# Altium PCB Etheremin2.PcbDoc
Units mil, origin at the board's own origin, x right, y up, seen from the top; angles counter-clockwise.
Board outline 6000 x 4000 mil, 2 copper layers (Top Layer, Bottom Layer); 40 components, 34 nets, 119 pads, 0 vias.
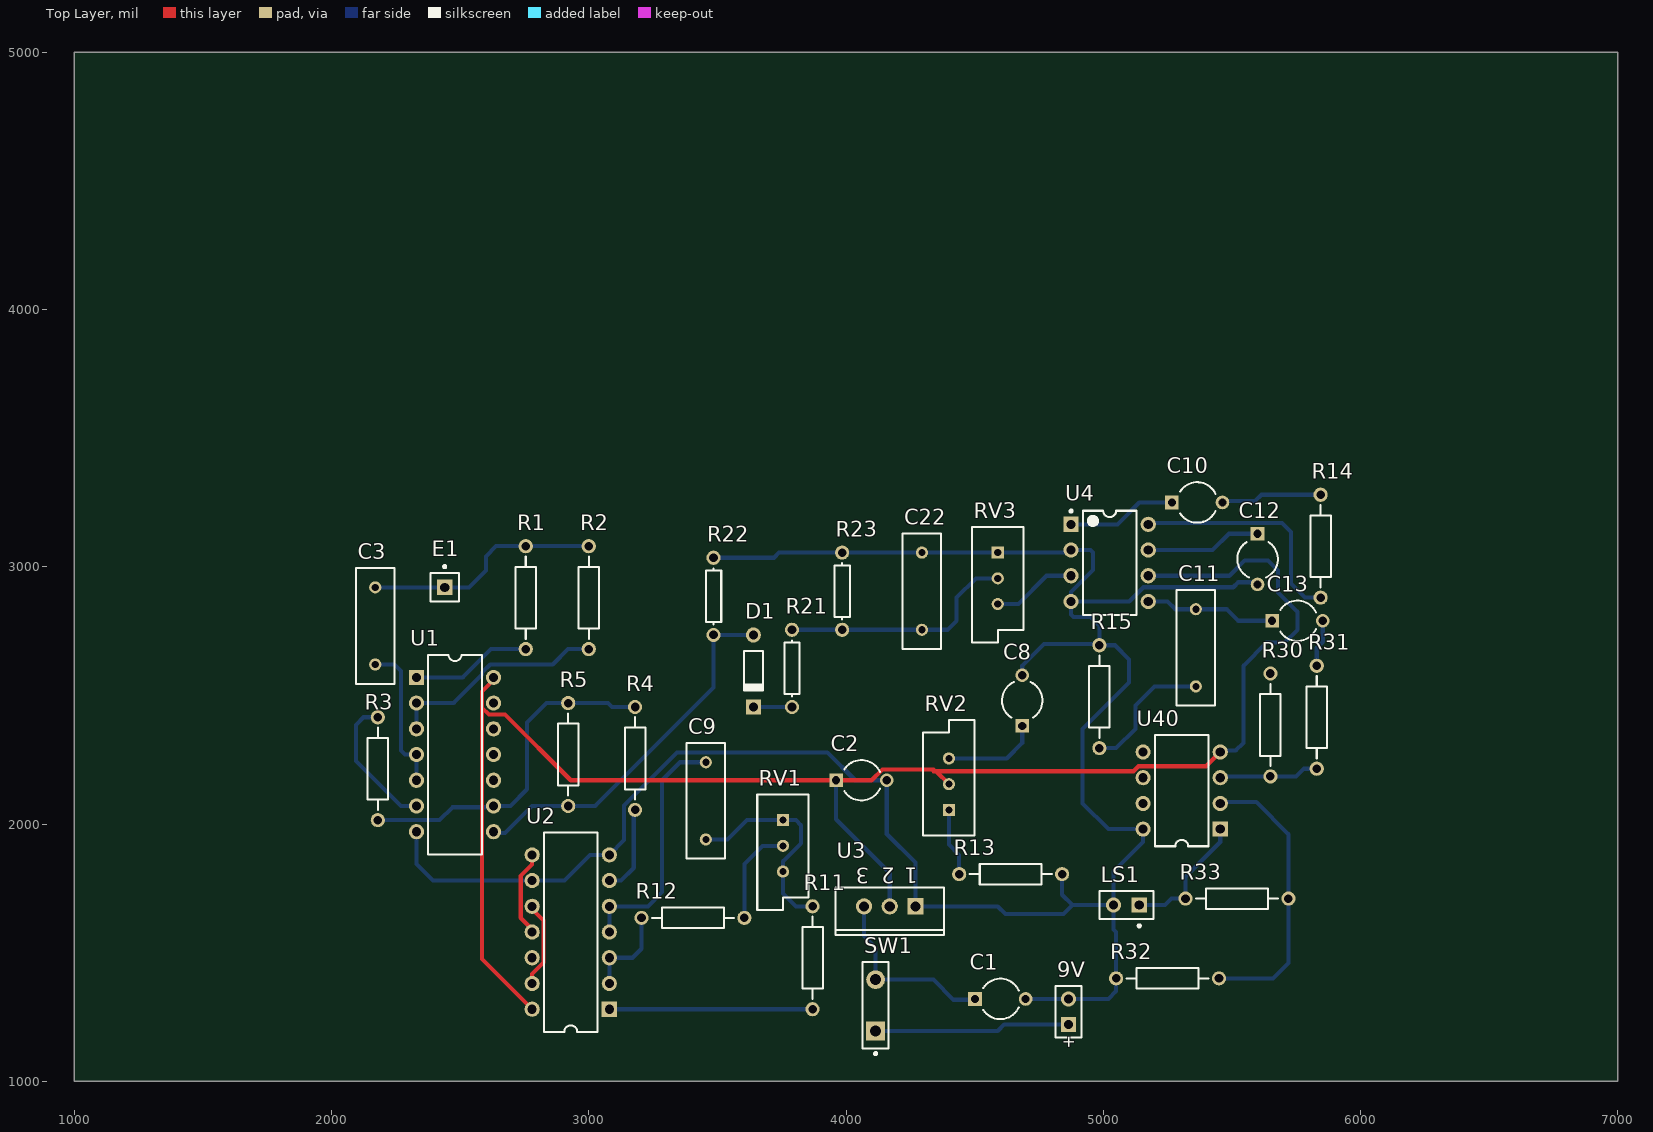
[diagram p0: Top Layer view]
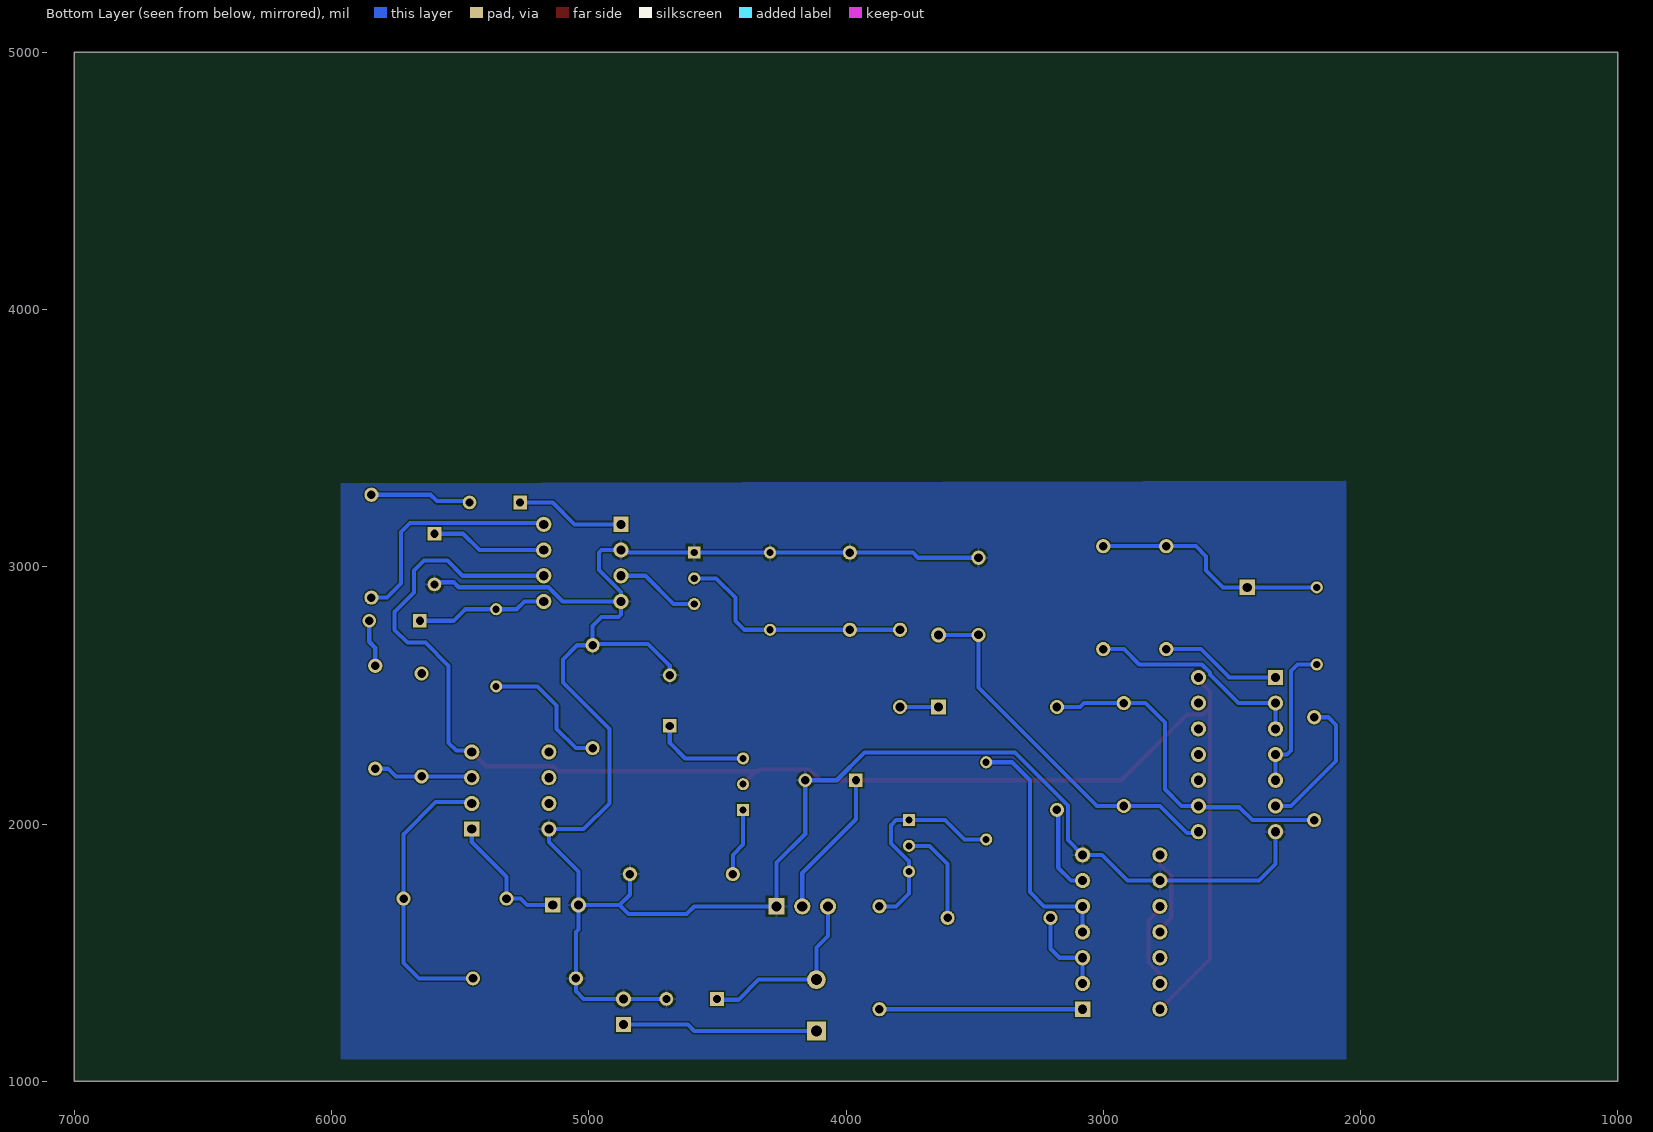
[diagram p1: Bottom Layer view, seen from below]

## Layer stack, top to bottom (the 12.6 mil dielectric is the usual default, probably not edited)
Top Layer: signal copper 1.4
Dielectric: dielectric 12.6, FR-4, Dk 4.8
Bottom Layer: signal copper 1.4

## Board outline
1000,1000 7000,1000 7000,5000 1000,5000

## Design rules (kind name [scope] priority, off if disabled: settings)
Clearance [All] p1: gap=5
PolygonConnect [All] p1: connectstyle=Relief reliefconductorwidth=10 reliefentries=4 polygonreliefangle="90 Angle" airgapwidth=10
RoomDefinition Etheremin2 [InComponentClass('Etheremin2')] p1: confinementstyle=ConfineIn formatcopy=TRUE lockcomponents=FALSE outline -465,-10 9495,-10 9495,890 -465,890
RoutingVias [All] p1: holewidth=28 width=50 viastyle="Through Hole" minholewidth=28 minwidth=50 maxholewidth=28 maxwidth=50
SilkscreenOverComponentPads [All] p1: minsilkscreentomaskgap=10
SolderMaskExpansion [All] p1: expansion=4
Width [All] p1: maxlimit=17 minlimit=10 preferedwidth=10
27 further rules are at their usual default settings.

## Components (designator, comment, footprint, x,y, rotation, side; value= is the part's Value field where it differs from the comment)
9V "Battery" BAT-2 4865,1270 r90 top
C1 "" CAPR5-4X5 4600,1320 r0 top
C2 "" CAPR5-4X5 4060,2170 r0 top
C3 "" RAD-0.3 2170,2770 r90 top
C8 "" CAPR5-4X5 4685,2480 r90 top
C9 "" RAD-0.3 3455,2090 r90 top
C10 "" CAPR5-4X5 5365,3250 r0 top
C11 "" RAD-0.3 5360,2685 r90 top
C12 "" CAPR5-4X5 5600,3030 r270 top
C13 "" CAPR5-4X5 5755,2790 r0 top
C22 "Cap" RAD-0.3 4295,2905 r270 top
D1 "Diode 1N4448" DO-35 3640,2595 r270 top
E1 "Antenna" PIN1 2440,2920 r0 top
LS1 "Speaker" PIN2 5140,1685 r180 top
R1 "" AXIAL-0.4 2755,2880 r90 top
R2 "" AXIAL-0.4 3000,2880 r90 top
R3 "" AXIAL-0.4 2180,2215 r90 top
R4 "" AXIAL-0.4 3180,2255 r270 top
R5 "" AXIAL-0.4 2920,2270 r90 top
R11 "" AXIAL-0.4 3870,1480 r270 top
R12 "" AXIAL-0.4 3405,1635 r180 top
R13 "" AXIAL-0.4 4640,1805 r0 top
R14 "" AXIAL-0.4 5845,3080 r270 top
R15 "" AXIAL-0.4 4985,2495 r90 top
R21 "Res1" AXIAL-0.3 3790,2605 r90 top
R22 "Res1" AXIAL-0.3 3485,2885 r270 top
R23 "Res1" AXIAL-0.3 3985,2905 r270 top
R30 "" AXIAL-0.4 5650,2385 r90 top
R31 "" AXIAL-0.4 5830,2415 r90 top
R32 "" AXIAL-0.4 5250,1400 r0 top
R33 "" AXIAL-0.4 5520,1710 r0 top
RV1 "" VR5 3755,1915 r270 top
RV2 "" VR5 4400,2155 r90 top
RV3 "" VR5 4590,2955 r270 top
SW1 "On-Off" SPST-2 4115,1295 r90 top
U1 "SN74LS04N" N014 2480,2270 r270 top
U2 "SN74LS04N" N014 2930,1580 r90 top
U3 "LM317KC" KC03 4170,1680 r180 top
U4 "LM386N-3" N08E 5025,3015 r0 top
U40 "LM193N" DIP8 5305,2130 r90 top

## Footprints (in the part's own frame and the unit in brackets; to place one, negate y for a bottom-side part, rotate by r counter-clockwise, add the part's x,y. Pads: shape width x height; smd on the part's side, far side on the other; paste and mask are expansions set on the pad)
AXIAL-0.3 [mm] "Axial Device, Thru-Hole; 2 Leads; 0.3 in Pin Spacing"
  round 1.4 hole 0.85: 1(-3.81,0) 2(3.81,0)
  silkscreen extent -2.77,-0.76 2.77,0.76
AXIAL-0.4 [mm] "Axial Device, Thru-Hole; 2 Leads; 0.4 in Pin Spacing"
  round 1.4 hole 0.85: 1(-5.08,0) 2(5.08,0)
  silkscreen extent -4.06,-1.02 4.06,1.02
BAT-2 [mm] "Battery; 2 Leads"
  rect 1.5x1.5 hole 0.9: 1(-1.27,0)
  round 1.5 hole 0.9: 2(1.27,0)
  silkscreen extent -2.54,-1.27 2.54,1.27
CAPR5-4X5 [mm] "Capacitor; 2 Leads"
  rect 1.35x1.35 hole 0.8: 1(-2.5,0)
  round 1.35 hole 0.8: 2(2.5,0)
  silkscreen extent -1.69,-2 1.82,2
DIP8 [mm] "DIP; 8 Leads; Row Spacing 7.62 mm; Pitch 2.54 mm"
  rect 1.5x1.5 hole 0.9: 1(-3.81,-3.81)
  round 1.5 hole 0.9: 2(-1.27,-3.81) 3(1.27,-3.81) 4(3.81,-3.81) 5(3.81,3.81) 6(1.27,3.81) 7(-1.27,3.81) 8(-3.81,3.81)
  silkscreen extent -5.5,-2.65 5.5,2.65
DO-35 [mm] "Diode, Axial; Body 3.8 x 1.9 mm (LxDia. max), Lead Dia. 0.53 mm (max)"
  round 1.5 hole 0.9: 1(-3.55,0)
  rect 1.5x1.5 hole 0.9: 2(3.55,0)
  silkscreen extent -1.95,-0.95 2.05,0.95
KC03 [mm] "TO, Thru-Hole, Vertical, Heatsink Mounted; 3 In-Line Leads; Pitch 2.54 mm"
  rect 1.6x1.6 hole 1: 1(-2.54,0)
  round 1.6 hole 1: 2(0,0) 3(2.54,0)
  silkscreen extent -5.35,-1.85 5.35,2.85
N08E [mm] "DIP, 8-Leads, Row Spacing 7.62mm, Pitch 2.54mm, Body 9.91x6.35mm"
  rect 1.5x1.5 hole 0.9: 1(-3.81,3.81)
  round 1.5 hole 0.9: 2(-3.81,1.27) 3(-3.81,-1.27) 4(-3.81,-3.81) 5(3.81,-3.81) 6(3.81,-1.27) 7(3.81,1.27) 8(3.81,3.81)
  silkscreen extent -3.93,-5.15 2.65,5.23, body extent -3.6,-5.15 3.6,5.15, height 5.34
N014 [mm] "DIP; 14 Leads; Row Spacing 7.62 mm; Pitch 2.54 mm"
  rect 1.5x1.5 hole 0.9: 1(-7.62,-3.81)
  round 1.5 hole 0.9: 2(-5.08,-3.81) 3(-2.54,-3.81) 4(0,-3.81) 5(2.54,-3.81) 6(5.08,-3.81) 7(7.62,-3.81) 8(7.62,3.81) 9(5.08,3.81) 10(2.54,3.81) 11(0,3.81) 12(-2.54,3.81) 13(-5.08,3.81) 14(-7.62,3.81)
  silkscreen extent -9.85,-2.65 9.85,2.65
PIN1 [mm] "Generic Antenna; 1 Lead"
  rect 1.5x1.5 hole 0.9: 1(0,0)
  silkscreen extent -1.4,-1.4 1.4,2.17
PIN2 [mm] "Photosensitive Diode; 2 Leads"
  rect 1.5x1.5 hole 0.9: 1(0,0)
  round 1.5 hole 0.9: 2(2.54,0)
  silkscreen extent -1.4,-1.4 3.94,2.17
RAD-0.3 [mm] "Radial Cap, Thru-Hole; 2 Leads; 0.3 in Pin Spacing"
  round 1.2 hole 0.7: 1(-3.81,0) 2(3.81,0)
  silkscreen extent -5.71,-1.91 5.71,1.91
SPST-2 [mm] "Switch; 2 Leads"
  rect 1.85x1.85 hole 1.1: 1(-2.54,0)
  round 1.85 hole 1.1: 2(2.54,0)
  silkscreen extent -4.89,-1.27 4.28,1.27
VR5 [mm] "Thru-Hole; 3 Leads"
  rect 1.2x1.2 hole 0.7: 1(-2.54,0)
  round 1.2 hole 0.7: 2(0,0) 3(2.54,0)
  silkscreen extent -5.08,-2.54 6.35,2.54

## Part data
9V: "Multicell Battery"
C1 C2 C8 C10 C12 C13: library part Cap2, "Capacitor"
C3 C9 C11: library part Cap, "Capacitor"
C22: "Capacitor"
D1: "High Conductance Fast Diode"
E1: "Generic Antenna"
LS1: "Loudspeaker"
R1 R2 R3 R4 R5 R11 R12 R13 R14 R15 R30 R31 R32 R33: library part Res2, "Resistor"
R21 R22 R23: "Resistor"
RV1 RV2 RV3: library part RPot, "Potentiometer"
SW1: library part SW-PB, "Switch"
U1 U2: "Hex Inverter"
U3: "3-Terminal Adjustable Regulator"
U4: "Low Voltage Audio Power Amplifier"
U40: "Low-Power Dual Voltage Comparator"

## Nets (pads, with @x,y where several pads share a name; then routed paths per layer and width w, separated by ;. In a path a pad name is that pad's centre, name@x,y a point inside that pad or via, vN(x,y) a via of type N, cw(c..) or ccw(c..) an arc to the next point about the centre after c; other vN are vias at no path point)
GND: 9V.2 C1.2 C2.2 C8.2 C12.2 C22.1 LS1.2 R13.2 R15.2 R22.1 R23.1 R32.1 RV3.1 U1.7 U2.7 U2.9 U3.1 U4.2 U4.4 U40.8 | length 8979.1
  Bottom Layer w10: U4.2@4865,3055 U4.2 ; R15.2@4980,2700 R15.2 ; C12.2@5591.57,2940 C12.2
  Bottom Layer w16: U1.7 2330,1845 2395,1780 U2.9 2905,1780 3005,1880 U2.7 3137.44,1937.44 3137.44,2072.63 3343.43,2278.62 3927.32,2278.62 4035.94,2170 C2.2 4158.43,1961.57 4270,1850 U3.1 4590,1680 4620,1650 4845,1650 4880,1685 ; R22.1 3720,3035 3740,3055 R23.1 C22.1 RV3.1 U4.2@4865,3055 ; C8.2 4685,2615 4770,2700 R15.2@4980,2700 ; C1.2 9V.2 5020,1320 5050,1350 R32.1 5050,1580 5040,1590 LS1.2 ; R13.2 4840,1725 4880,1685 ; U4.2 4950,3065 4960,3055 4960,2987.03 4875,2902.03 U4.4 ; C12.2@5591.57,2940 5525,2940 5505.47,2920.47 5156.56,2920.47 5101.08,2865 U4.4 ; U4.4 4875,2815 4885,2805 4950,2805 4985,2770 R15.2 5045,2695 5100,2640 5100,2550 4920,2370 4920,2080 5020,1980 U40.8 5155,1930 5040,1815 LS1.2 ; 4880,1685 LS1.2
Net9V_1: 9V.1 SW1.1 | length 760.4
  Bottom Layer w16: SW1.1 4590,1195 4615,1220 9V.1
NetC1_1: C1.1 SW1.2 U3.3 | length 731
  Bottom Layer w10: C1.1 C1.1@4505,1316.58
  Bottom Layer w16: U3.3 4070,1565 4115,1520 SW1.2 4340,1395 4418.43,1316.58 C1.1@4505,1316.58
NetC3_1: C3.1 U1.4 U1.5 | length 586.6
  Bottom Layer w16: C3.1 2245,2620 2270,2595 2270,2285 2285,2270 U1.4 U1.5
NetC3_2: C3.2 E1.1 R1.2 R2.2 | length 928.5
  Bottom Layer w16: C3.2 E1.1 2535,2920 2600,2985 2600,3040 2640,3080 R1.2 R2.2
NetC8_1: C8.1 RV2.3 | length 376.4
  Bottom Layer w16: RV2.3 4625,2255 4685,2315 C8.1
NetC9_1: C9.1 R11.1 RV1.1 RV1.3 | length 839.1
  Bottom Layer w16: C9.1 3540,1940 3615,2015 RV1.1 3805,2015 3825,1995 3825,1925 3755,1855 RV1.3 3755,1730 3805,1680 R11.1
NetC9_2: C9.2 U2.4 U2.5 | length 961.8
  Bottom Layer w16: U2.4 U2.5 3230,1680 3285,1735 3285,2170 3355,2240 C9.2
NetC10_1: C10.1 U4.1 | length 429
  Bottom Layer w10: C10.1@5265,3250 5265,3251.57 C10.1
  Bottom Layer w16: U4.1 5055,3165 5140,3250 C10.1@5265,3250
NetC10_2: C10.2 R14.1 | length 394
  Bottom Layer w10: C10.2 C10.2@5468.43,3255
  Bottom Layer w16: C10.2@5468.43,3255 5590,3255 5615,3280 R14.1
NetC11_1: C11.1 R15.1 | length 527.1
  Bottom Layer w16: R15.1 5050,2295 5125,2370 5125,2460 5200,2535 C11.1
NetC11_2: C11.2 C13.1 U4.5 | length 512.6
  Bottom Layer w16: U4.5 5250,2865 5280,2835 C11.2 5480,2835 5525,2790 C13.1
NetC12_1: C12.1 U4.7 | length 451.3
  Bottom Layer w16: U4.7 5425,3065 5488.43,3128.43 C12.1
NetC13_2: C13.2 R31.2 | length 184.7
  Bottom Layer w16: R31.2 5830,2685 5853.43,2708.43 C13.2
NetC22_2: C22.2 R21.2 R23.2 RV3.2 | length 935.6
  Bottom Layer w16: R21.2 R23.2 C22.2 4395,2755 4430,2790 4430,2880 4505,2955 RV3.2
NetD1_1: D1.1 R5.1 R22.2 U1.8 | length 1469.1
  Bottom Layer w10: D1.1@3639.76,2735 D1.1
  Bottom Layer w16: U1.8@2610,1965 2675,1965 2780,2070 R5.1 3025,2070 3485,2530 R22.2 D1.1@3639.76,2735
NetD1_2: D1.2 R21.1 | length 150.1
  Bottom Layer w10: D1.2 D1.2@3640.24,2455
  Bottom Layer w16: D1.2@3640.24,2455 R21.1
NetLS1_1: LS1.1 R33.1 U40.1 | length 521.3
  Bottom Layer w16: LS1.1 5240,1685 5265,1710 R33.1 5320,1795 5455,1930 U40.1@5455,1985
NetR1_1: R1.1 U1.1 | length 470.6
  Bottom Layer w16: U1.1 2510,2570 2620,2680 R1.1
NetR2_1: R2.1 U1.2 U1.3 | length 861.7
  Bottom Layer w10: 2585.47,2580.47 2585.47,2588.44
  Bottom Layer w16: U1.3 U1.2 2475,2470 2585.47,2580.47 ; 2585.47,2588.44 2617.03,2620 2860,2620 2920,2680 R2.1
NetR3_1: R3.1 R4.1 R5.2 U1.9 | length 1324.9
  Bottom Layer w16: R3.1 2420,2015 2470,2065 U1.9@2610,2065 ; U1.9 2695,2070 2760,2135 2760,2395 2835,2470 R5.2 3075,2470 3090,2455 R4.1
NetR3_2: R3.2 U1.6 | length 544.9
  Bottom Layer w16: R3.2 2125,2415 2095,2385 2095,2245 2270,2070 U1.6
NetR4_2: R4.2 U2.6 | length 342.8
  Bottom Layer w10: R4.2@3175,2050 R4.2
  Bottom Layer w16: U2.6 3125,1780 3175,1830 R4.2@3175,2050
NetR11_2: R11.2 U2.1 | length 805
  Bottom Layer w10: R11.2@3870,1285 R11.2@3870,1300
  Bottom Layer w16: U2.1 R11.2
NetR12_1: R12.1 RV1.2 | length 389
  Bottom Layer w16: R12.1 3605,1845 3675,1915 RV1.2
NetR12_2: R12.2 U2.2 U2.3 | length 359.5
  Bottom Layer w16: U2.2 U2.3 3170,1480 3205,1515 R12.2
NetR13_1: R13.1 RV2.1 | length 266.6
  Bottom Layer w16: RV2.1 4400,1920 4440,1880 R13.1
NetR14_2: R14.2 U4.8 | length 909.4
  Bottom Layer w10: U4.8 U4.8@5180,3170
  Bottom Layer w16: U4.8@5180,3170 5695,3170 5730,3135 5730,2935 5785,2880 R14.2
NetR30_1: R30.1 R31.1 U40.3 | length 387.4
  Bottom Layer w16: U40.3@5455,2185 R30.1 5750,2185 5780,2215 R31.1
NetR32_2: R32.2 R33.2 U40.2 | length 1111.6
  Bottom Layer w16: R32.2 5660,1400 5720,1460 R33.2 5720,1960 5595,2085 U40.2@5455,2085
NetRV3_3: RV3.3 U4.3 | length 330.6
  Bottom Layer w16: RV3.3 4670,2855 4780,2965 U4.3
NetU2_8: U2.8 U2.11 | length 336.9
  Top Layer w10: U2.11 U2.11@2780,1590.94
  Top Layer w16: U2.11@2780,1590.94 2735.47,1635.47 2735.47,1798.44 2780,1842.97 U2.8
NetU2_10: U2.10 U2.13 | length 336.9
  Top Layer w10: U2.10@2780,1669.06 U2.10
  Top Layer w16: U2.13 2780,1417.03 2824.53,1461.56 2824.53,1624.53 U2.10@2780,1669.06
VCC: C2.1 RV2.2 U1.14 U2.14 U3.2 U4.6 U40.4 | length 6548.4
  Top Layer w10: U1.14@2630,2559.05 U1.14
  Top Layer w16: U1.14@2630,2559.05 2585.47,2514.53 2585.47,2451.56 ; U2.14 2585.47,1474.53 2585.47,2451.56 ; 4340,2205 4350,2205 ; 4340,2211.57 4141.2,2211.57 4099.63,2170 C2.1 2930,2170 2674.53,2425.47 2611.56,2425.47 2585.47,2451.56 ; RV2.2 4350,2205 ; U40.4 5399.53,2224.53 5136.56,2224.53 5117.03,2205 4350,2205
  Bottom Layer w16: C2.1 3961.57,2018.43 4170,1810 U3.2 ; U4.6 5490,2965 5550,3025 5640,3025 5680,2985 5680,2900 5755,2825 5755,2755 5705,2705 5635,2705 5545,2615 5545,2315 5515,2285 U40.4@5455,2285
pads on no net: R30.2 U1.10 U1.11 U1.12 U1.13 U2.12 U40.5 U40.6 U40.7

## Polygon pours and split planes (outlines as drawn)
GND on Bottom Layer "masse" (solid, pour order 3): 5975,3325 5965,3335 5965,3340 5965,1085 5975,1075 5965,1085 2055,1085 2055,3330 2060,3335 2065,3335

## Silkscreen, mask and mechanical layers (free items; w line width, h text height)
Mechanical 1:
  lines w10: 2065,3340 2065,1140 2070,1135 2120,1085 ; 2070,3335 5970,3335 5970,1380 5970,1145 5970,1116.72 5933.28,1080 5925,1080 5905,1080 2120,1080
